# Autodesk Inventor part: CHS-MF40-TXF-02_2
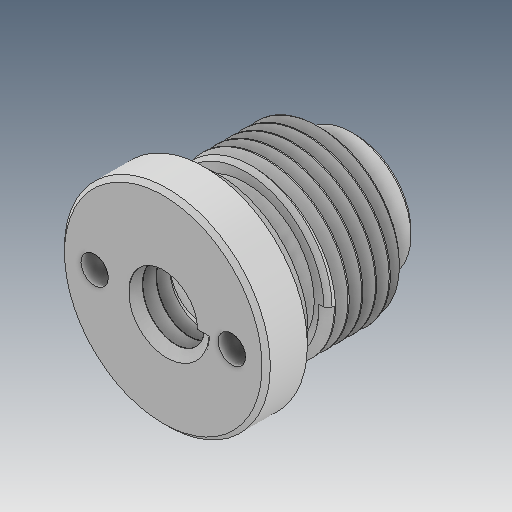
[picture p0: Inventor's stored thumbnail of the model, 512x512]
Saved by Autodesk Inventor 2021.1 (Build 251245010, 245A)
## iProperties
Created: 2019-04
Part Number: CHS-MF40-TXF-02_2
Material: Ogólny
Document SubType Name: Modeling
Designer: user
Density: 1 g/cm^3
Appearance: Domyślna
Author: user
Revision Number: ÈÎºÎ
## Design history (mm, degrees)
feature "ÊäÈë1"
node "Bryła1"
